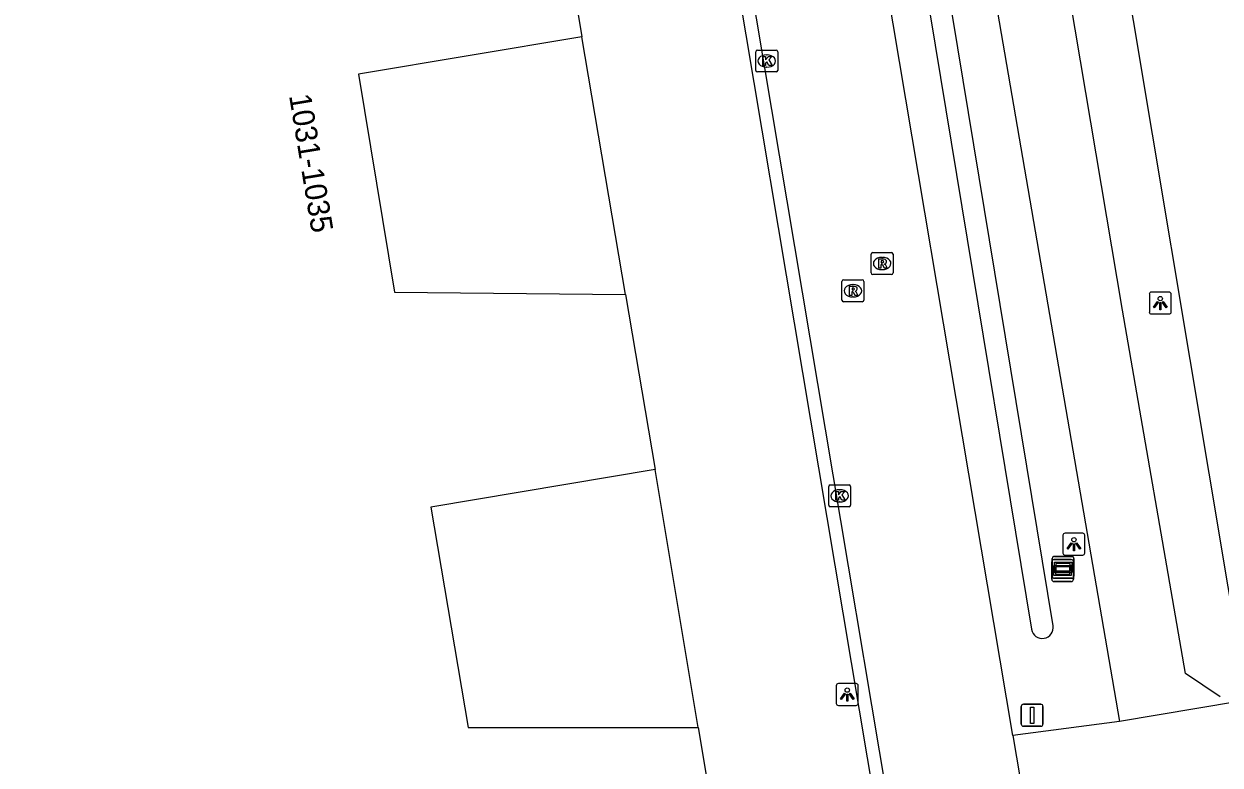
# Model space of a CAD drawing. Extents: x 154324 to 155743, y 382939 to 384183.
# Drawn here: x 155014.9 to 155069.4, y 383486.1 to 383519.9 of the extents above; entities that cross this region are included whole.
import ezdxf

# ---------------------------------------------------------------- set-up
doc = ezdxf.new("R2010")
doc.units = 0
for name, color, linetype in [('IMGEO_Fietspad_gesloten', 7, 'Continuous'), ('IMGEO_Greppel_droge_sloot', 7, 'Continuous'), ('IMGEO_Kolk', 7, 'Continuous'), ('IMGEO_Lichtpunt', 7, 'Continuous'), ('IMGEO_Pand', 7, 'Continuous'), ('IMGEO_Pand_nummerreeks', 7, 'Continuous'), ('IMGEO_Pand_overbouw', 7, 'Continuous'), ('IMGEO_Rijbaan_lokaal_gesloten', 7, 'Continuous'), ('IMGEO_Rijbaan_lokaal_open', 7, 'Continuous'), ('IMGEO_Rijbaan_regionaal_gesloten', 7, 'Continuous'), ('IMGEO_Rioolput', 7, 'Continuous'), ('IMGEO_Verkeersbordpaal', 7, 'Continuous'), ('IMGEO_Verklikker', 7, 'Continuous')]:
    doc.layers.add(name, color=color, linetype=linetype)

msp = doc.modelspace()

# ---------------------------------------------------------------- linework, layer by layer
at = {"layer": 'IMGEO_Fietspad_gesloten'}
for points in [[(155069.375, 383489.212), (155067.803, 383490.288), (155064.93, 383506.848), (155055.586, 383562.322), (155035.787, 383680.446), (155030.556, 383711.937), (155024.582, 383747.491), (155023.65, 383752.887)], [(155020.155, 383752.117), (155027.003, 383711.594), (155027.513, 383708.543), (155029.197, 383698.769), (155030.596, 383690.066), (155052.123, 383561.719), (155057.1, 383532.805), (155064.796, 383488.095)], [(155070.126, 383488.988), (155064.796, 383488.095)], [(155064.796, 383488.095), (155059.928, 383487.45)]]:
    msp.add_lwpolyline(points, dxfattribs=at)
at = {"layer": 'IMGEO_Greppel_droge_sloot'}
for points in [[(155040.514, 383615.174), (155060.78, 383492.297)], [(155061.766, 383492.46), (155041.5, 383615.337)]]:
    msp.add_lwpolyline(points, dxfattribs=at)
msp.add_arc((155061.273, 383492.379), 0.5, 189.4145, 9.3593, dxfattribs=at)
at = {"layer": 'IMGEO_Kolk'}
for p, q in [((155048.214, 383517.769), (155048.214, 383518.621)), ((155048.289, 383518.695), (155049.141, 383518.695)), ((155049.215, 383518.621), (155049.215, 383517.769)), ((155048.702, 383518.475), (155048.727, 383518.475)), ((155049.141, 383517.695), (155048.289, 383517.695)), ((155048.725, 383517.915), (155048.7, 383517.915)), ((155051.537, 383497.953), (155051.537, 383498.805)), ((155051.612, 383498.879), (155052.464, 383498.879)), ((155052.025, 383498.659), (155052.05, 383498.659)), ((155052.538, 383498.805), (155052.538, 383497.953)), ((155052.464, 383497.879), (155051.612, 383497.879)), ((155052.048, 383498.099), (155052.023, 383498.099))]:
    msp.add_line(p, q, dxfattribs=at)
for points in [[(155048.214, 383517.769), (155048.214, 383518.621)], [(155048.289, 383518.695), (155049.141, 383518.695)], [(155049.215, 383518.621), (155049.215, 383517.769)], [(155048.535, 383518.395), (155048.658, 383518.395), (155048.658, 383518.244), (155048.788, 383518.395), (155048.952, 383518.395), (155048.806, 383518.244), (155048.959, 383517.995), (155048.807, 383517.995), (155048.722, 383518.159), (155048.658, 383518.092), (155048.658, 383517.995), (155048.535, 383517.995), (155048.535, 383518.395)], [(155049.141, 383517.695), (155048.289, 383517.695)], [(155051.537, 383497.953), (155051.537, 383498.805)], [(155051.612, 383498.879), (155052.464, 383498.879)], [(155051.858, 383498.579), (155051.981, 383498.579), (155051.981, 383498.428), (155052.111, 383498.579), (155052.275, 383498.579), (155052.129, 383498.428), (155052.282, 383498.179), (155052.13, 383498.179), (155052.045, 383498.343), (155051.981, 383498.276), (155051.981, 383498.179), (155051.858, 383498.179), (155051.858, 383498.579)], [(155052.538, 383498.805), (155052.538, 383497.953)], [(155052.464, 383497.879), (155051.612, 383497.879)]]:
    msp.add_lwpolyline(points, dxfattribs=at)
for centre, start, end in [((155048.291, 383518.619), 91.552, 178.448), ((155048.291, 383518.619), 91.552, 178.448), ((155049.139, 383518.619), 1.552, 88.448), ((155049.139, 383518.619), 1.552, 88.448), ((155048.291, 383517.771), 181.552, 268.448), ((155048.291, 383517.771), 181.552, 268.448), ((155049.139, 383517.771), 271.552, 358.448), ((155049.139, 383517.771), 271.552, 358.448), ((155051.614, 383498.803), 91.552, 178.448), ((155051.614, 383498.803), 91.552, 178.448), ((155052.462, 383498.803), 1.552, 88.448), ((155052.462, 383498.803), 1.552, 88.448), ((155051.614, 383497.955), 181.552, 268.448), ((155051.614, 383497.955), 181.552, 268.448), ((155052.462, 383497.955), 271.552, 358.448), ((155052.462, 383497.955), 271.552, 358.448)]:
    msp.add_arc(centre, 0.0765, start, end, dxfattribs=at)
for centre, major_axis, ratio, start_param, end_param in [((155048.701, 383518.195), (-0.387, 0.002), 0.722429, 4.712389, 7.853982), ((155048.726, 383518.195), (-0.39, 0.002), 0.717154, 1.570796, 4.712389), ((155052.024, 383498.379), (-0.387, 0.002), 0.722429, 4.712389, 7.853982), ((155052.049, 383498.379), (-0.39, 0.002), 0.717154, 1.570796, 4.712389)]:
    msp.add_ellipse(centre, major_axis=major_axis, ratio=ratio, start_param=start_param, end_param=end_param, dxfattribs=at)
at = {"layer": 'IMGEO_Lichtpunt'}
for p, q in [((155067.053, 383507.664), (155066.245, 383507.664)), ((155067.053, 383507.664), (155066.245, 383507.664)), ((155066.151, 383507.569), (155066.151, 383506.762)), ((155066.151, 383507.569), (155066.151, 383506.762)), ((155067.147, 383506.762), (155067.147, 383507.569)), ((155067.147, 383506.762), (155067.147, 383507.569)), ((155066.245, 383506.668), (155067.053, 383506.668)), ((155066.245, 383506.668), (155067.053, 383506.668)), ((155062.214, 383496.579), (155062.214, 383495.772)), ((155062.214, 383496.579), (155062.214, 383495.772)), ((155063.116, 383496.674), (155062.308, 383496.674)), ((155063.116, 383496.674), (155062.308, 383496.674)), ((155063.21, 383495.772), (155063.21, 383496.579)), ((155063.21, 383495.772), (155063.21, 383496.579)), ((155062.308, 383495.678), (155063.116, 383495.678)), ((155062.308, 383495.678), (155063.116, 383495.678)), ((155051.885, 383489.726), (155051.885, 383488.919)), ((155051.885, 383489.726), (155051.885, 383488.919)), ((155052.787, 383489.821), (155051.979, 383489.821)), ((155052.787, 383489.821), (155051.979, 383489.821)), ((155052.881, 383488.919), (155052.881, 383489.726)), ((155052.881, 383488.919), (155052.881, 383489.726)), ((155051.979, 383488.825), (155052.787, 383488.825)), ((155051.979, 383488.825), (155052.787, 383488.825))]:
    msp.add_line(p, q, dxfattribs=at)
for points in [[(155066.525, 383507.233), (155066.564, 383507.205), (155066.376, 383506.943), (155066.338, 383506.97), (155066.525, 383507.233)], [(155066.627, 383507.185), (155066.674, 383507.185), (155066.674, 383506.863), (155066.627, 383506.863), (155066.627, 383507.185)], [(155066.737, 383507.205), (155066.775, 383507.232), (155066.962, 383506.97), (155066.923, 383506.942), (155066.737, 383507.205)], [(155062.588, 383496.243), (155062.627, 383496.215), (155062.439, 383495.953), (155062.401, 383495.98), (155062.588, 383496.243)], [(155062.8, 383496.215), (155062.838, 383496.242), (155063.025, 383495.98), (155062.986, 383495.952), (155062.8, 383496.215)], [(155062.69, 383496.195), (155062.737, 383496.195), (155062.737, 383495.873), (155062.69, 383495.873), (155062.69, 383496.195)], [(155052.259, 383489.39), (155052.298, 383489.362), (155052.11, 383489.1), (155052.072, 383489.127), (155052.259, 383489.39)], [(155052.361, 383489.342), (155052.408, 383489.342), (155052.408, 383489.02), (155052.361, 383489.02), (155052.361, 383489.342)], [(155052.471, 383489.362), (155052.509, 383489.389), (155052.696, 383489.127), (155052.657, 383489.099), (155052.471, 383489.362)]]:
    msp.add_lwpolyline(points, dxfattribs=at)
for centre in [(155066.65, 383507.367), (155062.713, 383496.377), (155052.384, 383489.524)]:
    msp.add_circle(centre, 0.0994, dxfattribs=at)
for centre, start, end in [((155066.245, 383507.569), 90, 180), ((155066.245, 383507.569), 90, 180), ((155067.053, 383507.569), 0, 90), ((155067.053, 383507.569), 0, 90), ((155066.245, 383506.762), 180, 270), ((155066.245, 383506.762), 180, 270), ((155067.053, 383506.762), 270, 0), ((155067.053, 383506.762), 270, 360), ((155062.308, 383496.579), 90, 180), ((155062.308, 383496.579), 90, 180), ((155063.116, 383496.579), 0, 90), ((155063.116, 383496.579), 0, 90), ((155062.308, 383495.772), 180, 270), ((155062.308, 383495.772), 180, 270), ((155063.116, 383495.772), 270, 0), ((155063.116, 383495.772), 270, 360), ((155051.979, 383489.726), 90, 180), ((155051.979, 383489.726), 90, 180), ((155052.787, 383489.726), 0, 90), ((155052.787, 383489.726), 0, 90), ((155051.979, 383488.919), 180, 270), ((155051.979, 383488.919), 180, 270), ((155052.787, 383488.919), 270, 0), ((155052.787, 383488.919), 270, 360)]:
    msp.add_arc(centre, 0.0946, start, end, dxfattribs=at)
at = {"layer": 'IMGEO_Pand'}
msp.add_lwpolyline([(154995.441, 383472.207), (154985.474, 383531.415), (155036.823, 383540.015), (155036.983, 383539.019), (155026.768, 383537.289), (155028.46, 383527.301), (155038.974, 383527.261), (155040.294, 383519.291), (155030.102, 383517.603), (155031.749, 383507.659), (155042.274, 383507.548), (155043.622, 383499.583), (155033.407, 383497.855), (155035.104, 383487.827), (155045.588, 383487.816), (155046.763, 383480.845), (154995.441, 383472.207)], dxfattribs=at)
at = {"layer": 'IMGEO_Pand_overbouw'}
for points in [[(155042.274, 383507.548), (155040.294, 383519.291), (155030.102, 383517.603), (155031.749, 383507.659)], [(155043.622, 383499.583), (155033.407, 383497.855), (155035.104, 383487.827), (155045.588, 383487.816)]]:
    msp.add_lwpolyline(points, close=True, dxfattribs=at)
at = {"layer": 'IMGEO_Rijbaan_lokaal_gesloten'}
for points in [[(155059.928, 383487.45), (155052.477, 383531.831), (155025.49, 383692.18), (155022.669, 383708.88), (155021.296, 383718.742)], [(155059.439, 383453.463), (155046.503, 383530.572), (155016.871, 383707.197)], [(155059.928, 383487.45), (155060.608, 383483.417)]]:
    msp.add_lwpolyline(points, dxfattribs=at)
at = {"layer": 'IMGEO_Rijbaan_lokaal_open'}
msp.add_lwpolyline([(155065.709, 383396.485), (155065.341, 383401.33), (155064.659, 383408.986), (155063.139, 383423.564), (155063.03, 383424.403), (155061.613, 383435.27), (155060.487, 383443.041), (155058.846, 383453.397), (155045.918, 383530.449), (155024.164, 383660.104), (155016.277, 383707.107)], dxfattribs=at)
at = {"layer": 'IMGEO_Rijbaan_regionaal_gesloten'}
msp.add_lwpolyline([(155023.592, 383759.163), (155025.319, 383747.582), (155031.523, 383712.699), (155040.998, 383657.511), (155047.66, 383620.638), (155058.726, 383558.566), (155063.68, 383530.41), (155070.593, 383489.047)], dxfattribs=at)
at = {"layer": 'IMGEO_Rioolput'}
for p, q in [((155053.473, 383508.54), (155053.473, 383509.392)), ((155053.548, 383509.466), (155054.4, 383509.466)), ((155054.474, 383509.392), (155054.474, 383508.54)), ((155053.961, 383509.246), (155053.986, 383509.246)), ((155052.216, 383508.224), (155053.068, 383508.224)), ((155054.4, 383508.466), (155053.548, 383508.466)), ((155053.984, 383508.686), (155053.959, 383508.686)), ((155052.141, 383507.298), (155052.141, 383508.15)), ((155052.629, 383508.004), (155052.654, 383508.004)), ((155053.142, 383508.15), (155053.142, 383507.298)), ((155053.068, 383507.224), (155052.216, 383507.224)), ((155052.652, 383507.444), (155052.627, 383507.444))]:
    msp.add_line(p, q, dxfattribs=at)
for points in [[(155053.473, 383508.54), (155053.473, 383509.392)], [(155053.548, 383509.466), (155054.4, 383509.466)], [(155054.474, 383509.392), (155054.474, 383508.54)], [(155054.062, 383509.164), (155053.81, 383509.166), (155053.81, 383508.766)], [(155053.81, 383508.766), (155053.934, 383508.766), (155053.934, 383508.928), (155053.945, 383508.928)], [(155053.988, 383509.085), (155053.934, 383509.085), (155053.934, 383509.004)], [(155053.934, 383509.004), (155053.986, 383509.004)], [(155053.992, 383508.899), (155054.063, 383508.766), (155054.203, 383508.766), (155054.138, 383508.892)], [(155052.216, 383508.224), (155053.068, 383508.224)], [(155054.4, 383508.466), (155053.548, 383508.466)], [(155052.141, 383507.298), (155052.141, 383508.15)], [(155052.73, 383507.922), (155052.478, 383507.924), (155052.478, 383507.524)], [(155052.478, 383507.524), (155052.602, 383507.524), (155052.602, 383507.686), (155052.613, 383507.686)], [(155052.656, 383507.843), (155052.602, 383507.843), (155052.602, 383507.762)], [(155052.602, 383507.762), (155052.654, 383507.762)], [(155053.142, 383508.15), (155053.142, 383507.298)], [(155053.068, 383507.224), (155052.216, 383507.224)], [(155052.66, 383507.657), (155052.731, 383507.524), (155052.871, 383507.524), (155052.806, 383507.65)]]:
    msp.add_lwpolyline(points, dxfattribs=at)
for centre, radius, start, end in [((155053.55, 383509.39), 0.0765, 91.552, 178.448), ((155053.55, 383509.39), 0.0765, 91.552, 178.448), ((155054.398, 383509.39), 0.0765, 1.552, 88.448), ((155054.398, 383509.39), 0.0765, 1.552, 88.448), ((155053.944, 383508.875), 0.0533, 26.0293, 88.6989), ((155053.97, 383509.193), 0.19, 274.7715, 282.9687), ((155053.994, 383508.989), 0.0964, 77.0061, 93.1865), ((155054.008, 383509.046), 0.0378, 276.6634, 79.6772), ((155054.061, 383509.054), 0.109, 350.3612, 89.416), ((155054.059, 383509.054), 0.112, 277.5842, 350.9817), ((155054.043, 383508.839), 0.108, 29.5134, 73.7905), ((155052.218, 383508.148), 0.0765, 91.552, 178.448), ((155052.218, 383508.148), 0.0765, 91.552, 178.448), ((155053.066, 383508.148), 0.0765, 1.552, 88.448), ((155053.066, 383508.148), 0.0765, 1.552, 88.448), ((155053.55, 383508.542), 0.0765, 181.552, 268.448), ((155053.55, 383508.542), 0.0765, 181.552, 268.448), ((155054.398, 383508.542), 0.0765, 271.552, 358.448), ((155054.398, 383508.542), 0.0765, 271.552, 358.448), ((155052.612, 383507.633), 0.0533, 26.0293, 88.6989), ((155052.638, 383507.951), 0.19, 274.7715, 282.9687), ((155052.662, 383507.747), 0.0964, 77.0061, 93.1865), ((155052.676, 383507.804), 0.0378, 276.6634, 79.6772), ((155052.729, 383507.812), 0.109, 350.3612, 89.416), ((155052.727, 383507.812), 0.112, 277.5842, 350.9817), ((155052.711, 383507.597), 0.108, 29.5134, 73.7905), ((155052.218, 383507.3), 0.0765, 181.552, 268.448), ((155052.218, 383507.3), 0.0765, 181.552, 268.448), ((155053.066, 383507.3), 0.0765, 271.552, 358.448), ((155053.066, 383507.3), 0.0765, 271.552, 358.448)]:
    msp.add_arc(centre, radius, start, end, dxfattribs=at)
for centre, major_axis, ratio, start_param, end_param in [((155053.96, 383508.966), (-0.387, 0.002), 0.722429, 4.712389, 7.853982), ((155053.985, 383508.966), (-0.39, 0.002), 0.717154, 1.570796, 4.712389), ((155052.628, 383507.724), (-0.387, 0.002), 0.722429, 4.712389, 7.853982), ((155052.653, 383507.724), (-0.39, 0.002), 0.717154, 1.570796, 4.712389)]:
    msp.add_ellipse(centre, major_axis=major_axis, ratio=ratio, start_param=start_param, end_param=end_param, dxfattribs=at)
at = {"layer": 'IMGEO_Verkeersbordpaal'}
for p, q in [((155060.314, 383487.979), (155060.314, 383488.779)), ((155060.314, 383488.779), (155060.314, 383487.979)), ((155060.414, 383488.879), (155061.204, 383488.879)), ((155061.204, 383488.879), (155060.414, 383488.879)), ((155061.304, 383488.779), (155061.304, 383487.979)), ((155061.304, 383487.979), (155061.304, 383488.779)), ((155061.204, 383487.879), (155060.414, 383487.879)), ((155060.414, 383487.879), (155061.204, 383487.879))]:
    msp.add_line(p, q, dxfattribs=at)
msp.add_lwpolyline([(155060.734, 383488.754), (155060.884, 383488.754), (155060.884, 383488.004), (155060.734, 383488.004), (155060.734, 383488.754)], dxfattribs=at)
for centre, start, end in [((155060.414, 383488.779), 90, 180), ((155060.414, 383488.779), 90, 180), ((155061.204, 383488.779), 0, 90), ((155061.204, 383488.779), 360, 90), ((155060.414, 383487.979), 180, 270), ((155060.414, 383487.979), 180, 270), ((155061.204, 383487.979), 270, 0), ((155061.204, 383487.979), 270, 0)]:
    msp.add_arc(centre, 0.1, start, end, dxfattribs=at)
at = {"layer": 'IMGEO_Verklikker'}
for p, q in [((155061.704, 383494.574), (155061.704, 383495.374)), ((155061.704, 383495.374), (155061.704, 383494.574)), ((155061.723, 383494.721), (155061.723, 383495.521)), ((155061.723, 383495.521), (155061.723, 383494.721)), ((155061.804, 383495.474), (155062.594, 383495.474)), ((155062.594, 383495.474), (155061.804, 383495.474)), ((155061.823, 383495.621), (155062.613, 383495.621)), ((155062.613, 383495.621), (155061.823, 383495.621)), ((155062.694, 383495.374), (155062.694, 383494.574)), ((155062.694, 383494.574), (155062.694, 383495.374)), ((155062.713, 383495.521), (155062.713, 383494.721)), ((155062.713, 383494.721), (155062.713, 383495.521)), ((155062.613, 383494.621), (155061.823, 383494.621)), ((155061.823, 383494.621), (155062.613, 383494.621)), ((155062.594, 383494.474), (155061.804, 383494.474)), ((155061.804, 383494.474), (155062.594, 383494.474))]:
    msp.add_line(p, q, dxfattribs=at)
for points in [[(155061.805, 383495.206), (155062.593, 383495.206), (155062.593, 383494.742), (155061.805, 383494.742), (155061.805, 383495.206)], [(155061.824, 383495.353), (155062.612, 383495.353), (155062.612, 383494.889), (155061.824, 383494.889), (155061.824, 383495.353)], [(155061.87, 383495.141), (155061.87, 383494.807), (155062.528, 383494.807), (155062.528, 383495.141), (155061.87, 383495.141)], [(155061.889, 383495.288), (155061.889, 383494.954), (155062.547, 383494.954), (155062.547, 383495.288), (155061.889, 383495.288)]]:
    msp.add_lwpolyline(points, dxfattribs=at)
for centre, start, end in [((155061.804, 383495.374), 90, 180), ((155061.804, 383495.374), 90, 180), ((155061.823, 383495.521), 90, 180), ((155061.823, 383495.521), 90, 180), ((155062.594, 383495.374), 0, 90), ((155062.594, 383495.374), 360, 90), ((155062.613, 383495.521), 0, 90), ((155062.613, 383495.521), 360, 90), ((155061.823, 383494.721), 180, 270), ((155061.823, 383494.721), 180, 270), ((155062.613, 383494.721), 270, 0), ((155062.613, 383494.721), 270, 0), ((155061.804, 383494.574), 180, 270), ((155061.804, 383494.574), 180, 270), ((155062.594, 383494.574), 270, 0), ((155062.594, 383494.574), 270, 0)]:
    msp.add_arc(centre, 0.1, start, end, dxfattribs=at)

# ---------------------------------------------------------------- texts
at = {"layer": 'IMGEO_Pand_nummerreeks'}
msp.add_text('1031-1035', height=1, rotation=279.4029, dxfattribs=at).set_placement((155026.94, 383516.621))

doc.saveas('drawing.dxf')
